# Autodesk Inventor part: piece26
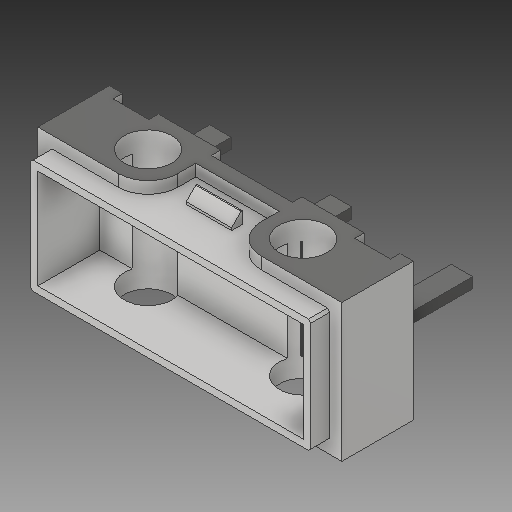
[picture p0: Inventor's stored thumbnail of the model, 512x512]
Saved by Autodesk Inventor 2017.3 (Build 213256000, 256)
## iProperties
Created: 2002-06
Part Number: piece26
Material: Générique
Document SubType Name: Modeling
Designer: ficho
Density: 1 g/cm^3
Appearance: Par défaut
Author: ficho
Sending System: SolidWorks 2009
Last Author: christophe
Last Saved: 2011-02-10
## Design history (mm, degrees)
feature "Enlèv. mat.-Extru.3"
node "Solide1"
